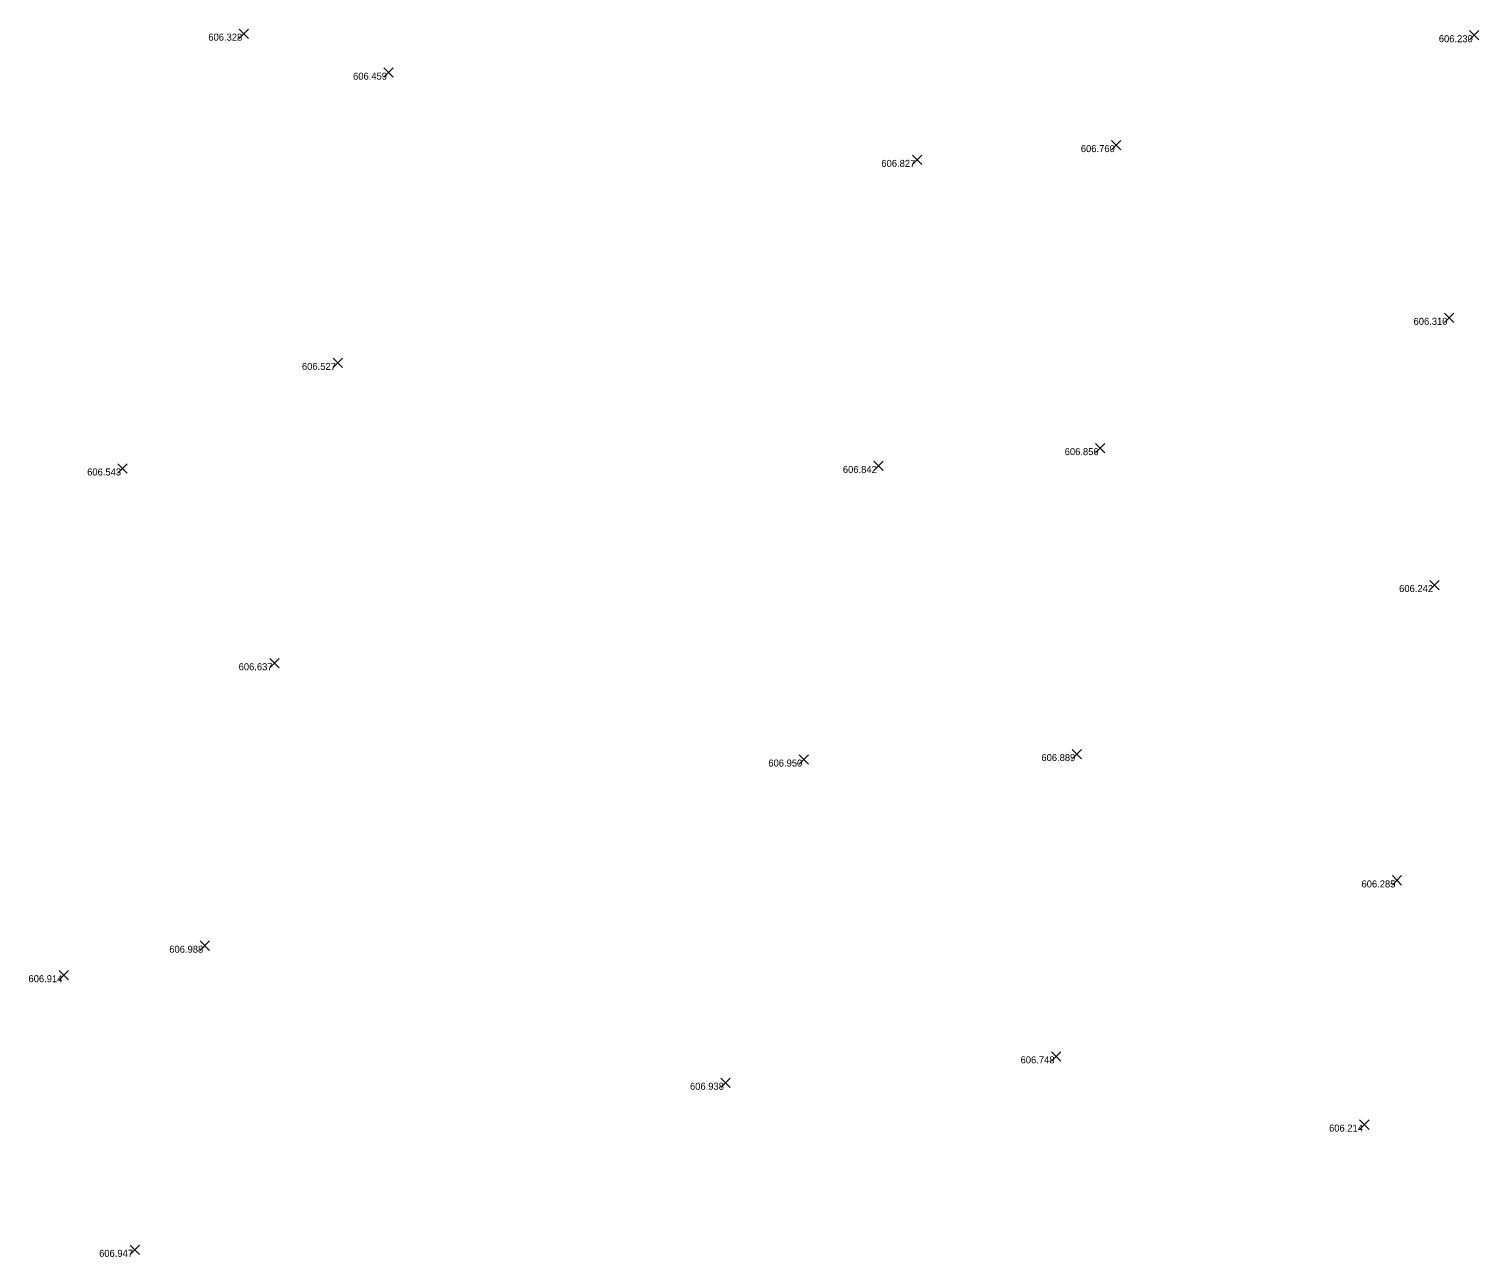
# Model space of a CAD drawing. Extents: x -2 to 1979875, y -2 to 232027.
# Drawn here: x 1978644.3 to 1978747.6, y 231363.7 to 231451.2 of the extents above; entities that cross this region are included whole.
import ezdxf

# ---------------------------------------------------------------- set-up
doc = ezdxf.new("R2010")
doc.units = 0
doc.layers.add('_CIVIL_CONSTRUCTION', color=7, linetype='Continuous')
doc.layers.add('SV_X_Random_Point', color=7, linetype='Continuous')

msp = doc.modelspace()

# ---------------------------------------------------------------- linework, layer by layer
at = {"layer": 'SV_X_Random_Point'}
for p, q in [((1978659.31, 231450.52), (1978659.97, 231451.19)), ((1978659.31, 231451.19), (1978659.97, 231450.52)), ((1978746.95, 231450.42), (1978747.62, 231451.09)), ((1978746.95, 231451.09), (1978747.62, 231450.42)), ((1978669.61, 231447.75), (1978670.27, 231448.42)), ((1978669.61, 231448.42), (1978670.27, 231447.75)), ((1978721.45, 231442.58), (1978722.12, 231443.25)), ((1978721.45, 231443.25), (1978722.12, 231442.58)), ((1978707.27, 231441.54), (1978707.93, 231442.21)), ((1978707.27, 231442.21), (1978707.93, 231441.54)), ((1978745.16, 231430.29), (1978745.82, 231430.96)), ((1978745.16, 231430.96), (1978745.82, 231430.29)), ((1978666, 231427.08), (1978666.67, 231427.74)), ((1978666, 231427.74), (1978666.67, 231427.08)), ((1978720.31, 231421), (1978720.98, 231421.67)), ((1978720.31, 231421.67), (1978720.98, 231421)), ((1978650.67, 231419.56), (1978651.34, 231420.23)), ((1978650.67, 231420.23), (1978651.34, 231419.56)), ((1978704.51, 231419.74), (1978705.17, 231420.4)), ((1978704.51, 231420.4), (1978705.17, 231419.74)), ((1978744.12, 231411.25), (1978744.79, 231411.92)), ((1978744.12, 231411.92), (1978744.79, 231411.25)), ((1978661.49, 231405.69), (1978662.15, 231406.36)), ((1978661.49, 231406.36), (1978662.15, 231405.69)), ((1978718.64, 231399.21), (1978719.3, 231399.88)), ((1978718.64, 231399.88), (1978719.3, 231399.21)), ((1978699.2, 231398.82), (1978699.86, 231399.49)), ((1978699.2, 231399.49), (1978699.86, 231398.82)), ((1978741.45, 231390.22), (1978742.11, 231390.89)), ((1978741.45, 231390.89), (1978742.11, 231390.22)), ((1978656.52, 231385.57), (1978657.19, 231386.24)), ((1978656.52, 231386.24), (1978657.19, 231385.57)), ((1978646.49, 231383.47), (1978647.15, 231384.14)), ((1978646.49, 231384.14), (1978647.15, 231383.47)), ((1978717.17, 231377.68), (1978717.84, 231378.35)), ((1978717.17, 231378.35), (1978717.84, 231377.68)), ((1978693.62, 231375.8), (1978694.29, 231376.47)), ((1978693.62, 231376.47), (1978694.29, 231375.8)), ((1978739.12, 231372.82), (1978739.79, 231373.49)), ((1978739.12, 231373.49), (1978739.79, 231372.82)), ((1978651.54, 231363.9), (1978652.21, 231364.57)), ((1978651.54, 231364.57), (1978652.21, 231363.9))]:
    msp.add_line(p, q, dxfattribs=at)

# ---------------------------------------------------------------- texts
at = {"layer": '_CIVIL_CONSTRUCTION'}
for s, p in [('606.328', (1978657.11, 231450.36)), ('606.230', (1978744.76, 231450.25)), ('606.459', (1978667.42, 231447.58)), ('606.760', (1978719.26, 231442.42)), ('606.827', (1978705.05, 231441.37)), ('606.310', (1978742.96, 231430.12)), ('606.527', (1978663.78, 231426.91)), ('606.856', (1978718.11, 231420.84)), ('606.543', (1978648.48, 231419.39)), ('606.842', (1978702.31, 231419.57)), ('606.242', (1978741.93, 231411.09)), ('606.637', (1978659.27, 231405.52)), ('606.889', (1978716.45, 231399.05)), ('606.950', (1978697, 231398.66)), ('606.285', (1978739.25, 231390.05)), ('606.988', (1978654.33, 231385.4)), ('606.914', (1978644.3, 231383.3)), ('606.748', (1978714.97, 231377.52)), ('606.938', (1978691.42, 231375.64)), ('606.214', (1978736.94, 231372.66)), ('606.947', (1978649.33, 231363.74))]:
    msp.add_text(s, height=0.5, dxfattribs=at).set_placement(p)

doc.saveas('drawing.dxf')
